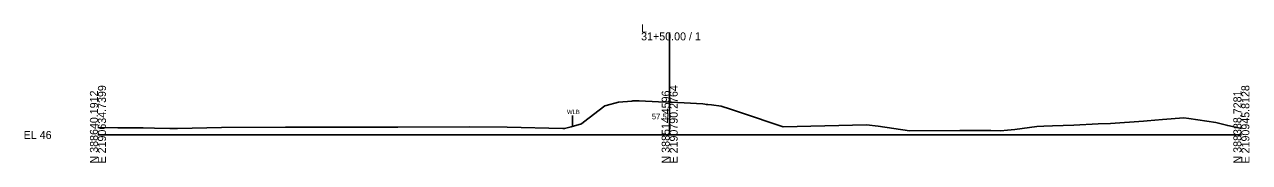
# Model space of a CAD drawing. Extents: x -26 to 2190750, y -10 to 388496.
# Drawn here: x 974.3 to 1402.8, y 5490.3 to 5538.8 of the extents above; entities that cross this region are included whole.
import ezdxf

# ---------------------------------------------------------------- set-up
doc = ezdxf.new("R2010")
doc.units = 0
for name, color, linetype in [('Default', 7, 'Continuous'), ('Exist Cross Section Cell', 7, 'Continuous'), ('Exist XS Center Line Elevation Label', 7, 'Continuous'), ('Exist XS Ground Line', 7, 'Continuous'), ('Prop RDY Alternate Text Blue', 7, 'Continuous')]:
    doc.layers.add(name, color=color, linetype=linetype)

msp = doc.modelspace()

# ---------------------------------------------------------------- linework, layer by layer
at = {"layer": 'Exist Cross Section Cell'}
for p, q in [((1200, 5500), (1200, 5536.02)), ((1000, 5500), (1200, 5500)), ((1200, 5500), (1400, 5500))]:
    msp.add_line(p, q, dxfattribs=at)
at = {"layer": 'Exist XS Ground Line'}
msp.add_lwpolyline([(1000, 5502.66), (1006.98, 5502.52), (1015.8, 5502.47), (1019.84, 5502.43), (1025.14, 5502.31), (1027.84, 5502.29), (1043.28, 5502.57), (1065.62, 5502.77), (1089.19, 5502.72), (1104.96, 5502.8), (1129.93, 5502.86), (1143.16, 5502.72), (1162.6, 5502.25), (1163.23, 5502.23), (1165.57, 5502.91), (1169.18, 5503.96), (1169.84, 5504.51), (1177.36, 5510.18), (1177.81, 5510.32), (1182.1, 5511.51), (1186.76, 5511.93), (1187.17, 5511.97), (1187.99, 5512.01), (1188.3, 5512.01), (1189.36, 5511.95), (1196.11, 5511.66), (1200, 5511.5), (1200.63, 5511.47), (1205.09, 5511.24), (1211.58, 5510.89), (1212.25, 5510.81), (1212.72, 5510.76), (1213.35, 5510.65), (1214.68, 5510.53), (1218.04, 5510.09), (1221.25, 5509.04), (1225.14, 5507.82), (1239.39, 5502.98), (1239.7, 5502.87), (1268.89, 5503.61), (1272.89, 5503.12), (1283.93, 5501.49), (1301.56, 5501.54), (1312.35, 5501.55), (1315.76, 5501.48), (1318.2, 5501.64), (1320.79, 5501.91), (1328.48, 5502.92), (1330.93, 5503.1), (1333.97, 5503.19), (1341.34, 5503.44), (1349.88, 5503.86), (1354.2, 5504.03), (1365.78, 5504.87), (1367.06, 5504.98), (1372.44, 5505.38), (1379.92, 5505.97), (1381.65, 5505.78), (1391.04, 5504.33), (1395.25, 5503.32), (1400, 5502.29)], dxfattribs=at)
at = {"layer": 'Prop RDY Alternate Text Blue'}
msp.add_line((1166, 5506.86), (1166, 5503.04), dxfattribs=at)

# ---------------------------------------------------------------- texts
at = {"layer": 'Default'}
msp.add_text('-', height=0.0001, dxfattribs=at).set_placement((1000, 5500))
at = {"layer": 'Exist Cross Section Cell'}
for s, p in [('L', (1190, 5536.02)), ('31+50.00 / 1', (1190, 5533.22)), ('EL 46', (974, 5498.6))]:
    msp.add_text(s, height=2.8, dxfattribs=at).set_placement(p)
for s, p in [('N 388640.1912', (1000, 5490)), ('E 2190634.7399', (1002.8, 5490)), ('N 388514.4596', (1200, 5490)), ('E 2190790.2764', (1202.8, 5490)), ('N 388388.7281', (1400, 5490)), ('E 2190945.8128', (1402.8, 5490))]:
    msp.add_text(s, height=2.8, rotation=90, dxfattribs=at).set_placement(p)
at = {"layer": 'Exist XS Center Line Elevation Label'}
msp.add_text('57.50', height=2, dxfattribs=at).set_placement((1193.76, 5505.5))
at = {"layer": 'Prop RDY Alternate Text Blue'}
msp.add_text('WLB', height=1.5, dxfattribs=at).set_placement((1164.08, 5507.33))

doc.saveas('drawing.dxf')
